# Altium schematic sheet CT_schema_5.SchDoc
size 385 x 185 mm
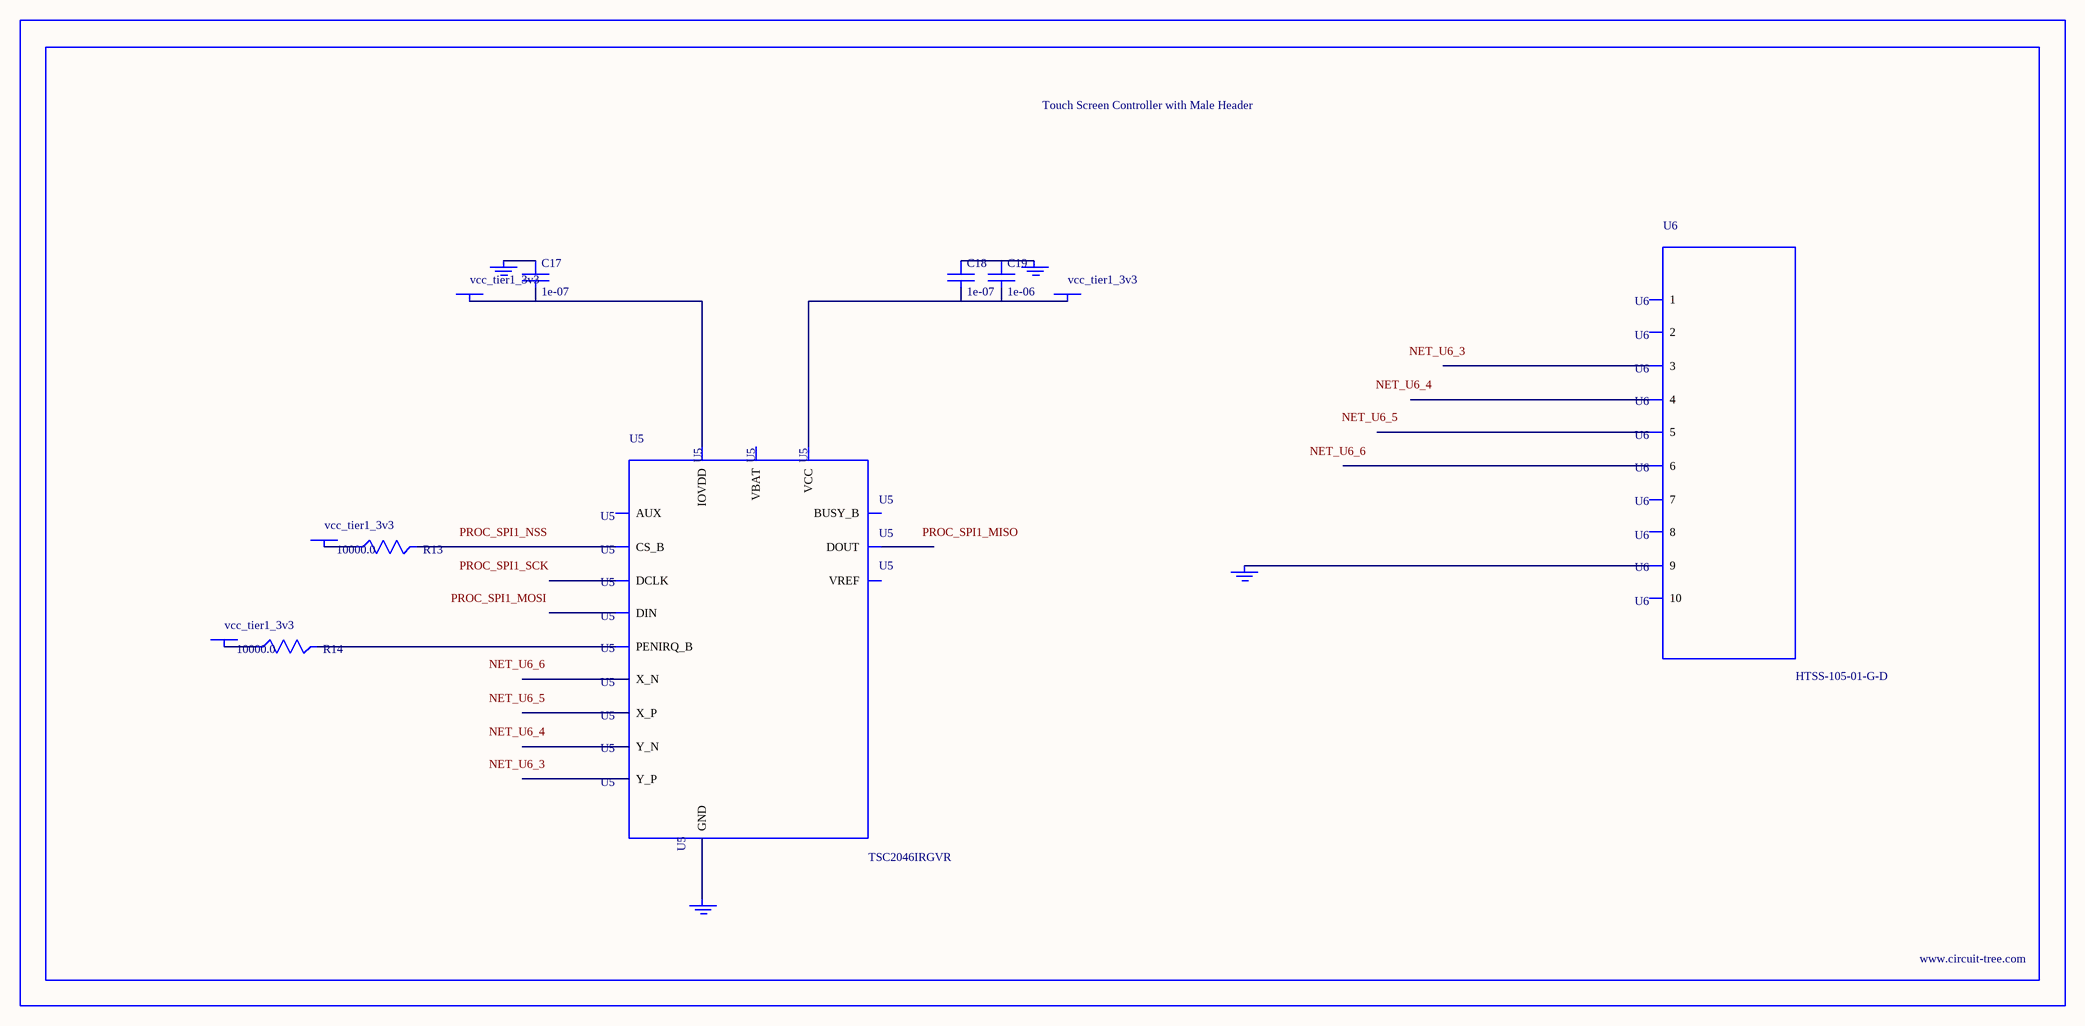
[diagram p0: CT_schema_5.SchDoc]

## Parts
BORDER4  (no value)
C17  1e-07  [C0402]
C18  1e-07  [C0402]
C19  1e-06  [C0603]
GND_INSTANCE_4_0  (no value)
GND_INSTANCE_4_1  (no value)
GND_INSTANCE_4_2  (no value)
GND_INSTANCE_4_3  (no value)
POWER_INSTANCE_4_0  vcc_tier1_3v3
POWER_INSTANCE_4_1  vcc_tier1_3v3
POWER_INSTANCE_4_2  vcc_tier1_3v3
POWER_INSTANCE_4_3  vcc_tier1_3v3
R13  10000.0  [R0603]
R14  10000.0  [R0603]
U5  TSC2046IRGVR  [VQFN-16]
U6  HTSS-105-01-G-D  [HTSS-105-01-G-D]

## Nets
NetC17_1: C17.1 GND_INSTANCE_4_1.0(GND)
NetC17_2: C17.2 POWER_INSTANCE_4_2.0(PWR) U5.14(IOVDD)
NetC18_1: C18.1 C19.1 GND_INSTANCE_4_0.0(GND)
NetC18_2: C18.2 C19.2 POWER_INSTANCE_4_1.0(PWR) U5.5(VCC)
NetGND_INSTANCE_4_2_0: GND_INSTANCE_4_2.0(GND) U5.10(GND)
NetGND_INSTANCE_4_3_0: GND_INSTANCE_4_3.0(GND) U6.9
NetPOWER_INSTANCE_4_0_0: POWER_INSTANCE_4_0.0(PWR) R13.1
NetPOWER_INSTANCE_4_3_0: POWER_INSTANCE_4_3.0(PWR) R14.1
NetR13_2: R13.2 U5.3(CS_B)
NetR14_2: R14.2 U5.15(PENIRQ_B)

Not connected (* = marked no-connect by the designer): U5 1(BUSY_B) 2(DIN) 4(DCLK) 6(X_P) 7(Y_P) 8(X_N) 9(Y_N) 11(VBAT) 12(AUX) 13(VREF) 16(DOUT); U6 1 2 3 4 5 6 7 8 10

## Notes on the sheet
- Labels drawn without touching a wire or pin: NET_U6_3, NET_U6_4, NET_U6_5, NET_U6_6, PROC_SPI1_MISO, PROC_SPI1_MOSI, PROC_SPI1_NSS, PROC_SPI1_SCK

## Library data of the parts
BORDER4 = BORDER_PAGE4
C17 C18 = C0402C104K3RACTU
C19 = C0603C105K3RACTU
GND_INSTANCE_4_0-GND_INSTANCE_4_3 = GND
POWER_INSTANCE_4_0-POWER_INSTANCE_4_3 = PWR
R13 R14 = RC0603JR-0710KL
